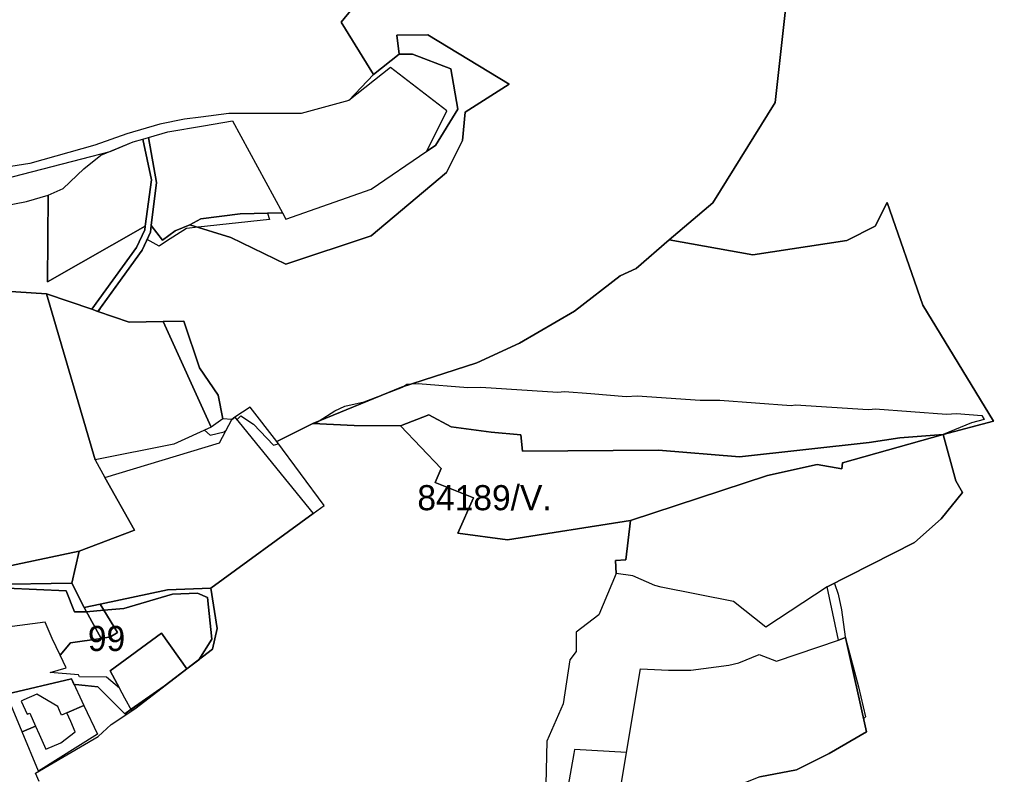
# Model space of a CAD drawing. Extents: x -477304 to -465429, y -1159113 to -1149210.
# Drawn here: x -475194 to -474612, y -1153906 to -1153455 of the extents above; entities that cross this region are included whole.
import ezdxf

# ---------------------------------------------------------------- set-up
doc = ezdxf.new("R2010")
doc.units = 0
for name, color, linetype in [('BPEJ_s', 7, 'Continuous'), ('PUPFL_s', 7, 'Continuous'), ('trav_porost_s', 7, 'Continuous')]:
    doc.layers.add(name, color=color, linetype=linetype)

msp = doc.modelspace()

# ---------------------------------------------------------------- linework, layer by layer
at = {"layer": 'BPEJ_s'}
for points in [[(-475210.5, -1153551.5), (-475157.21, -1153537.77), (-475140.18, -1153533.38), (-475126.37, -1153527.64), (-475120.66, -1153525.96), (-475117.3, -1153524.97), (-475105.79, -1153521.59), (-475084.49, -1153518.17), (-475067.07, -1153514.99), (-475037.22, -1153570.16), (-475046.12, -1153570.33), (-475045, -1153574), (-475087.54, -1153578.73), (-475094.5, -1153579.5), (-475106.5, -1153587), (-475111, -1153590), (-475118.11, -1153586), (-475121.02, -1153592.41), (-475146.02, -1153626.88), (-475146.6, -1153627.77), (-475147.42, -1153629.01), (-475128.78, -1153635.35), (-475108.55, -1153635), (-475079.85, -1153698.22), (-475083.88, -1153700.04), (-475080.5, -1153703), (-475072, -1153701), (-475070.93, -1153699.98), (-475067.57, -1153693.55), (-475065.63, -1153692.27)], [(-475210.5, -1153551.5), (-475157.21, -1153537.77), (-475140.18, -1153533.38), (-475126.37, -1153527.64), (-475120.66, -1153525.96), (-475117.3, -1153524.97), (-475105.79, -1153521.59), (-475084.49, -1153518.17), (-475067.07, -1153514.99), (-475037.22, -1153570.16), (-475046.12, -1153570.33), (-475045, -1153574), (-475087.54, -1153578.73), (-475094.5, -1153579.5), (-475106.5, -1153587), (-475111, -1153590), (-475118.11, -1153586), (-475121.02, -1153592.41), (-475146.02, -1153626.88), (-475146.6, -1153627.77), (-475147.42, -1153629.01), (-475128.78, -1153635.35), (-475108.55, -1153635), (-475079.85, -1153698.22), (-475083.88, -1153700.04), (-475080.5, -1153703), (-475072, -1153701), (-475070.93, -1153699.98), (-475067.57, -1153693.55), (-475065.63, -1153692.27), (-475064.4, -1153693.78), (-475062, -1153691.5), (-475054.5, -1153696.5), (-475042.5, -1153709), (-475039.72, -1153708.07), (-475040.64, -1153706.84), (-475019.08, -1153695.95), (-475017.81, -1153696.01), (-475015.26, -1153694.39), (-475006, -1153688.5), (-475000, -1153685.65), (-474988.47, -1153683.02), (-474970.67, -1153676.22), (-474965.48, -1153674.24), (-474965.37, -1153674.17), (-474965.21, -1153674.07), (-474962.92, -1153672.54), (-474959.9, -1153672.35), (-474956.11, -1153672.11), (-474926.33, -1153674.45), (-474918.67, -1153674.24), (-474872.7, -1153677.22), (-474868.66, -1153676.8), (-474852.96, -1153678.07), (-474831.85, -1153679.77), (-474825.26, -1153679.56), (-474787.59, -1153682.11), (-474775.68, -1153682.11), (-474733.12, -1153685.31), (-474730.57, -1153684.88), (-474687.16, -1153687.65), (-474684.77, -1153687.41), (-474682.91, -1153687.22), (-474640.35, -1153690.41), (-474634.39, -1153689.99), (-474619.07, -1153691.26), (-474617.74, -1153693.7), (-474625.38, -1153695.7), (-474642.19, -1153702.55), (-474634.76, -1153730.2), (-474630.77, -1153737.29), (-474643.45, -1153753.07), (-474659.32, -1153767.19), (-474707.66, -1153791.56), (-474707.16, -1153791.7), (-474705.03, -1153798.08), (-474703.12, -1153807.44), (-474700.78, -1153823.61), (-474700.67, -1153823.98), (-474700.59, -1153824.36), (-474692.95, -1153853.47), (-474688.65, -1153871.28), (-474689.85, -1153872.61), (-474688.14, -1153880.3), (-474710.35, -1153893.29), (-474730.02, -1153903.05), (-474751.79, -1153907.13)], [(-475065.63, -1153692.27), (-475064.4, -1153693.78), (-475062, -1153691.5), (-475054.5, -1153696.5), (-475042.5, -1153709), (-475039.72, -1153708.07), (-475040.64, -1153706.84), (-475019.08, -1153695.95), (-475017.81, -1153696.01), (-475015.26, -1153694.39), (-475006, -1153688.5), (-475000, -1153685.65), (-474988.47, -1153683.02), (-474970.67, -1153676.22), (-474965.48, -1153674.24), (-474965.37, -1153674.17), (-474965.21, -1153674.07), (-474962.92, -1153672.54), (-474959.9, -1153672.35), (-474956.11, -1153672.11), (-474926.33, -1153674.45), (-474918.67, -1153674.24), (-474872.7, -1153677.22), (-474868.66, -1153676.8), (-474852.96, -1153678.07), (-474831.85, -1153679.77), (-474825.26, -1153679.56), (-474787.59, -1153682.11), (-474775.68, -1153682.11), (-474733.12, -1153685.31), (-474730.57, -1153684.88), (-474687.16, -1153687.65), (-474684.77, -1153687.41), (-474682.91, -1153687.22), (-474640.35, -1153690.41), (-474634.39, -1153689.99), (-474619.07, -1153691.26), (-474617.74, -1153693.7), (-474625.38, -1153695.7), (-474642.19, -1153702.55), (-474634.76, -1153730.2), (-474630.77, -1153737.29), (-474643.45, -1153753.07), (-474659.32, -1153767.19), (-474707.66, -1153791.56), (-474707.16, -1153791.7), (-474705.03, -1153798.08), (-474703.12, -1153807.44), (-474700.78, -1153823.61), (-474700.67, -1153823.98), (-474700.59, -1153824.36), (-474692.95, -1153853.47), (-474688.65, -1153871.28), (-474689.85, -1153872.61), (-474688.14, -1153880.3), (-474710.35, -1153893.29), (-474730.02, -1153903.05), (-474751.79, -1153907.13)], [(-475202, -1153794.5), (-475166.5, -1153796), (-475161.5, -1153808.5), (-475154.5, -1153808.5), (-475154.36, -1153808.49), (-475144.04, -1153807.57), (-475132, -1153806.5), (-475103, -1153798), (-475088, -1153797.5), (-475082, -1153800), (-475079.5, -1153825), (-475087.19, -1153837.21), (-475094.29, -1153842.65), (-475107.85, -1153853.1), (-475127.69, -1153866.86), (-475131.5, -1153869.5), (-475133.2, -1153867.8), (-475140.35, -1153860.65), (-475147.26, -1153853.74), (-475147.5, -1153853.5), (-475155.1, -1153852.66), (-475161, -1153852), (-475161.7, -1153852.22), (-475163.36, -1153848.67), (-475202.25, -1153857.8)], [(-475202.25, -1153857.8), (-475163.36, -1153848.67), (-475161.7, -1153852.22), (-475161, -1153852), (-475155.1, -1153852.66), (-475147.5, -1153853.5), (-475147.26, -1153853.74), (-475140.35, -1153860.65), (-475133.2, -1153867.8), (-475131.5, -1153869.5), (-475127.69, -1153866.86), (-475107.85, -1153853.1), (-475094.29, -1153842.65), (-475087.19, -1153837.21), (-475079.5, -1153825), (-475082, -1153800), (-475088, -1153797.5), (-475103, -1153798), (-475132, -1153806.5), (-475144.04, -1153807.57), (-475154.36, -1153808.49), (-475154.5, -1153808.5), (-475161.5, -1153808.5), (-475166.5, -1153796), (-475202, -1153794.5)], [(-474836.11, -1153920.21), (-474831.55, -1153892.73), (-474862.73, -1153890.78), (-474863.13, -1153893.19), (-474866.75, -1153914.68)], [(-474836.11, -1153920.21), (-474831.55, -1153892.73), (-474862.73, -1153890.78), (-474863.13, -1153893.19), (-474866.75, -1153914.68)]]:
    msp.add_lwpolyline(points, dxfattribs=at)
at = {"layer": 'PUPFL_s'}
for points in [[(-475210.14, -1153365.57), (-475086.3, -1153337.96), (-474971.29, -1153418.32), (-475002.11, -1153456.19), (-474982.86, -1153487.39), (-474997.56, -1153502.86), (-475026.08, -1153510.65), (-475069.36, -1153510.76), (-475086.09, -1153512.85), (-475095.81, -1153514.09), (-475110.59, -1153517.18), (-475130.22, -1153522.83), (-475149.39, -1153529.67), (-475188.27, -1153540.51), (-475207.41, -1153543.59)], [(-474735.34, -1153437.58), (-474742.68, -1153504.05), (-474779.95, -1153564.01), (-474806.08, -1153586.24), (-474825.82, -1153603.27), (-474835.45, -1153607.68), (-474862.59, -1153628.77), (-474895.53, -1153647.89), (-474921, -1153659.79), (-474965.97, -1153674.31), (-475019.08, -1153695.95), (-475040.64, -1153706.84), (-475056.45, -1153686.24), (-475065.63, -1153692.27), (-475067.57, -1153693.55), (-475072.94, -1153693.16), (-475075.72, -1153679.13), (-475086.8, -1153662.73), (-475096.08, -1153634.79), (-475108.55, -1153635), (-475128.78, -1153635.35), (-475147.54, -1153628.97), (-475121.02, -1153592.41), (-475116.11, -1153581.58), (-475115.67, -1153577.59), (-475109.02, -1153586.46), (-475101.26, -1153580.77), (-475092.52, -1153577.19), (-475068, -1153584.76), (-475035.25, -1153600.81), (-474984.1, -1153583.81), (-474939.2, -1153545.88), (-474929.6, -1153526.81), (-474927.92, -1153509.81), (-474901.73, -1153493.17), (-474950.33, -1153463.65), (-474968.82, -1153463.8), (-474967.51, -1153475.3), (-474982.86, -1153487.39), (-475002.11, -1153456.19), (-474971.29, -1153418.32)], [(-474751.79, -1153907.13), (-474730.02, -1153903.05), (-474710.35, -1153893.29), (-474688.14, -1153880.3), (-474700.67, -1153823.98), (-474704.82, -1153825.5), (-474710.21, -1153800.12), (-474711.61, -1153793.55), (-474659.32, -1153767.19), (-474643.45, -1153753.07), (-474630.77, -1153737.29), (-474634.76, -1153730.2), (-474642.19, -1153702.55), (-474612.18, -1153694.54), (-474654.47, -1153625.24), (-474675.82, -1153563.86), (-474682.84, -1153578.01), (-474699.9, -1153586.64), (-474756.1, -1153595.21), (-474806.08, -1153586.24), (-474779.95, -1153564.01), (-474742.68, -1153504.05), (-474735.34, -1153437.58)]]:
    msp.add_lwpolyline(points, dxfattribs=at)
for points in [[(-475068, -1153584.76), (-475092.52, -1153577.19), (-475086.04, -1153573.69), (-475062.54, -1153570.63), (-475037.22, -1153570.16), (-475035.18, -1153573.8), (-474984.1, -1153555.93), (-474950.99, -1153533.18), (-474945.82, -1153529.77), (-474932.33, -1153508.08), (-474936.62, -1153483.93), (-474959.43, -1153475.16), (-474967.51, -1153475.3), (-474968.82, -1153463.8), (-474950.33, -1153463.65), (-474901.73, -1153493.17), (-474927.92, -1153509.81), (-474929.6, -1153526.81), (-474939.2, -1153545.88), (-474984.1, -1153583.81), (-475035.25, -1153600.81)], [(-474972.6, -1153483.16), (-474997.56, -1153502.86), (-474982.86, -1153487.39), (-474967.51, -1153475.3), (-474959.43, -1153475.16), (-474936.62, -1153483.93), (-474932.33, -1153508.08), (-474945.82, -1153529.77), (-474950.99, -1153533.18), (-474938.91, -1153509.19)], [(-474763.99, -1153716.02), (-474812.44, -1153711.97), (-474893.73, -1153712.54), (-474894.75, -1153702.75), (-474912.46, -1153701.11), (-474936.42, -1153698.02), (-474949.63, -1153690.86), (-474966.6, -1153697.31), (-474994.43, -1153697.21), (-475019.08, -1153695.95), (-474965.97, -1153674.31), (-474921, -1153659.79), (-474895.53, -1153647.89), (-474862.59, -1153628.77), (-474835.45, -1153607.68), (-474825.82, -1153603.27), (-474806.08, -1153586.24), (-474756.1, -1153595.21), (-474699.9, -1153586.64), (-474682.84, -1153578.01), (-474675.82, -1153563.86), (-474654.47, -1153625.24), (-474612.18, -1153694.54), (-474642.19, -1153702.55), (-474668.1, -1153704.59), (-474686.52, -1153707.45)], [(-475072.94, -1153693.16), (-475079.85, -1153698.22), (-475108.55, -1153635), (-475096.08, -1153634.79), (-475086.8, -1153662.73), (-475075.72, -1153679.13)], [(-475145.68, -1153824.43), (-475163.99, -1153827.18), (-475170.15, -1153834.41), (-475174.82, -1153824.59), (-475178.99, -1153814.69), (-475209.54, -1153818.83), (-475212.6, -1153792.16), (-475163.12, -1153791.49), (-475155.68, -1153806.07)], [(-475170.15, -1153834.41), (-475163.99, -1153827.18), (-475145.68, -1153824.43), (-475140.09, -1153823.55), (-475135.77, -1153820.99), (-475146.22, -1153804.03), (-475105.99, -1153795.34), (-475079.94, -1153794.52), (-475076.27, -1153818.64), (-475078.97, -1153830.92), (-475094.29, -1153842.65), (-475109.45, -1153821.29), (-475140.28, -1153843.93), (-475134.66, -1153854.17), (-475142.32, -1153847.63), (-475158.59, -1153847.37), (-475159.2, -1153846.3), (-475176.04, -1153844.83), (-475166.52, -1153842.1)], [(-475135.77, -1153820.99), (-475140.09, -1153823.55), (-475145.68, -1153824.43), (-475155.68, -1153806.07), (-475146.22, -1153804.03)], [(-475094.29, -1153842.65), (-475124.57, -1153865.98), (-475127.23, -1153867.69), (-475131.35, -1153860.2), (-475134.66, -1153854.17), (-475140.28, -1153843.93), (-475109.45, -1153821.29)]]:
    msp.add_lwpolyline(points, close=True, dxfattribs=at)
at = {"layer": 'trav_porost_s'}
for points in [[(-475086.04, -1153573.69), (-475092.52, -1153577.19), (-475101.26, -1153580.77), (-475109.02, -1153586.46), (-475115.67, -1153577.59), (-475112.56, -1153551.94), (-475117.3, -1153524.97), (-475105.79, -1153521.59), (-475084.49, -1153518.17), (-475067.07, -1153514.99), (-475037.22, -1153570.16), (-475062.54, -1153570.63)], [(-475147.54, -1153628.97), (-475151.09, -1153627.76), (-475124.5, -1153590.75), (-475119.47, -1153580.22), (-475119.33, -1153578.07), (-475115.51, -1153550.4), (-475120.66, -1153525.96), (-475117.3, -1153524.97), (-475112.56, -1153551.94), (-475115.67, -1153577.59), (-475116.11, -1153581.58), (-475121.02, -1153592.41)], [(-475115.51, -1153550.4), (-475119.33, -1153578.07), (-475177.74, -1153611.24), (-475177.22, -1153559.5), (-475168.34, -1153555.54), (-475155.98, -1153543.74), (-475145.8, -1153535.71), (-475126.37, -1153527.64), (-475120.66, -1153525.96)], [(-475177.74, -1153611.24), (-475119.33, -1153578.07), (-475119.47, -1153580.22), (-475124.5, -1153590.75), (-475151.09, -1153627.76), (-475178.33, -1153618.5), (-475212.23, -1153616.22), (-475237.76, -1153619.12), (-475238.02, -1153615.32), (-475239.41, -1153589.93), (-475242.7, -1153580.69), (-475239.09, -1153579.19), (-475212.03, -1153567.45), (-475190.2, -1153563.38), (-475177.22, -1153559.5)], [(-475234.27, -1153669.52), (-475237.76, -1153619.12), (-475212.23, -1153616.22), (-475178.33, -1153618.5), (-475149.26, -1153717.69), (-475143.43, -1153728.23), (-475125.7, -1153759.77), (-475158.82, -1153772.41), (-475213.55, -1153783.85), (-475226.06, -1153786), (-475234.63, -1153790.84), (-475243, -1153769.96), (-475256.01, -1153733.93), (-475261.21, -1153721.59), (-475228.64, -1153706.57), (-475239.85, -1153674.85), (-475243.11, -1153675.6), (-475245.8, -1153669.52)], [(-475151.09, -1153627.76), (-475147.54, -1153628.97), (-475128.78, -1153635.35), (-475108.55, -1153635), (-475079.85, -1153698.22), (-475102.17, -1153708.32), (-475149.26, -1153717.69), (-475178.33, -1153618.5)], [(-475143.43, -1153728.23), (-475074.91, -1153707.61), (-475067.57, -1153693.55), (-475065.63, -1153692.27), (-475018.91, -1153749.8), (-475079.94, -1153794.52), (-475105.99, -1153795.34), (-475146.22, -1153804.03), (-475155.68, -1153806.07), (-475163.12, -1153791.49), (-475158.82, -1153772.41), (-475125.7, -1153759.77)], [(-474717.65, -1153720.52), (-474747.34, -1153727.16), (-474829.16, -1153753.94), (-474902.61, -1153765.48), (-474932.32, -1153761.52), (-474923.1, -1153740.36), (-474945.99, -1153731.36), (-474942.37, -1153722.99), (-474966.6, -1153697.31), (-474949.63, -1153690.86), (-474936.42, -1153698.02), (-474912.46, -1153701.11), (-474894.75, -1153702.75), (-474893.73, -1153712.54), (-474812.44, -1153711.97), (-474763.99, -1153716.02), (-474686.52, -1153707.45), (-474668.1, -1153704.59), (-474642.19, -1153702.55), (-474702.48, -1153719.47), (-474702.78, -1153723.16)], [(-474634.76, -1153730.2), (-474630.77, -1153737.29), (-474643.45, -1153753.07), (-474659.32, -1153767.19), (-474711.61, -1153793.55), (-474748.19, -1153817.67), (-474767.6, -1153802.34), (-474810.81, -1153793.9), (-474814.55, -1153792.85), (-474827.68, -1153787.16), (-474837.76, -1153785.62), (-474838.21, -1153777.98), (-474831.97, -1153777.53), (-474829.16, -1153753.94), (-474747.34, -1153727.16), (-474717.65, -1153720.52), (-474702.78, -1153723.16), (-474702.48, -1153719.47), (-474642.19, -1153702.55)], [(-475212.6, -1153792.16), (-475213.55, -1153783.85), (-475158.82, -1153772.41), (-475163.12, -1153791.49)], [(-474700.67, -1153823.98), (-474688.14, -1153880.3), (-474710.35, -1153893.29), (-474730.02, -1153903.05), (-474751.79, -1153907.13), (-474766.41, -1153912.91), (-474783.13, -1153917.58), (-474817.54, -1153920.94), (-474836.11, -1153920.21), (-474823.24, -1153842.58), (-474806.42, -1153843.43), (-474793.05, -1153843.38), (-474770.49, -1153840.38), (-474764.45, -1153839.08), (-474752.18, -1153834.09), (-474742, -1153838.13), (-474704.82, -1153825.5)], [(-475202.25, -1153857.8), (-475163.36, -1153848.67), (-475155.95, -1153864.55), (-475166.06, -1153868.88), (-475169.35, -1153870.28), (-475169.5, -1153869.91), (-475171.49, -1153865.27), (-475183.98, -1153857.72), (-475191.83, -1153861.23), (-475193.34, -1153861.91), (-475189.82, -1153869.78), (-475188.31, -1153869.11), (-475184.78, -1153876.88), (-475192.84, -1153880.33)], [(-475166.06, -1153868.88), (-475155.95, -1153864.55), (-475147.79, -1153881.75), (-475182.95, -1153903.76), (-475192.84, -1153880.33), (-475184.78, -1153876.88), (-475182.65, -1153881.73), (-475178.71, -1153890.68), (-475169.71, -1153886.82), (-475161.19, -1153880.28), (-475163.78, -1153874.21)]]:
    msp.add_lwpolyline(points, close=True, dxfattribs=at)
msp.add_lwpolyline([(-475182.65, -1153910.04), (-475184.89, -1153904.97), (-475147.44, -1153883.15), (-475139.69, -1153875.88), (-475127.23, -1153867.69), (-475124.57, -1153865.98), (-475094.29, -1153842.65), (-475078.97, -1153830.92), (-475076.27, -1153818.64), (-475079.94, -1153794.52), (-475018.91, -1153749.8), (-475012.31, -1153744.97), (-475040.64, -1153706.84), (-475019.08, -1153695.95), (-474994.43, -1153697.21), (-474966.6, -1153697.31), (-474942.37, -1153722.99), (-474945.99, -1153731.36), (-474923.1, -1153740.36), (-474932.32, -1153761.52), (-474902.61, -1153765.48), (-474829.16, -1153753.94), (-474831.97, -1153777.53), (-474838.21, -1153777.98), (-474837.76, -1153785.62), (-474848.17, -1153810.28), (-474861.7, -1153820.82), (-474861.75, -1153832.37), (-474865.52, -1153837.18), (-474869.45, -1153863.49), (-474879.15, -1153885.96), (-474880.06, -1153920.54)], dxfattribs=at)

# ---------------------------------------------------------------- texts
at = {"layer": 'BPEJ_s'}
for s, p in [('84189/V.', (-474956.58, -1153747.85)), ('99', (-475153.52, -1153832))]:
    msp.add_text(s, height=15, dxfattribs=at).set_placement(p)

doc.saveas('drawing.dxf')
